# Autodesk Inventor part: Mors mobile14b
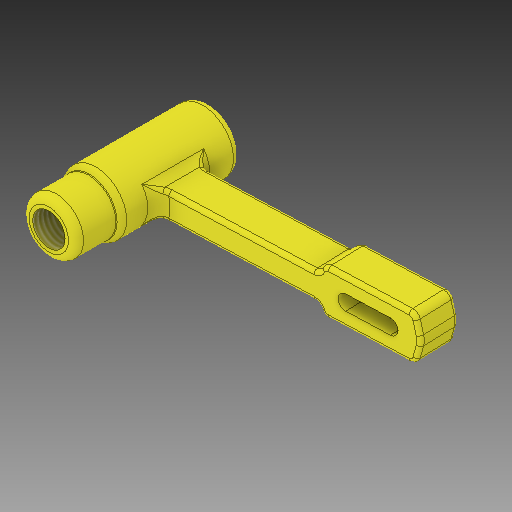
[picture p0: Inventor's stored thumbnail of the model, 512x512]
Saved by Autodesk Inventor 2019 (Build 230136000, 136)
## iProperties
Created: 2000-02
Part Number: Mors mobile14b
Material: Générique
Document SubType Name: Modeling
Designer: si-nd67
Density: 1 g/cm^3
Appearance: Jaune canari
Mass: 77.433 g
Surface Area: 266.449 cm^2
Volume: 77.433 cm^3
Sending System: SolidWorks 2014
Last Author: tjost
Last Saved: 2019-02-07
Author: si-nd67
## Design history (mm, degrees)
feature "Enlèv. mat.-Extru.6"
sketch "Esquisse1"
  geometry: 2 further points
  constraints: 1 coincident
hole "Perçage1" sketch "Esquisse1" at (0, 0) diameter "d0" = 17.294; stored, may be unused: countersink angle "d4" = 90 deg, drill point angle "d6" = 0 deg; dims "d1" = 40, "d2" = 4, "d3" = 2, "d5" = 40
node "Solide1"
